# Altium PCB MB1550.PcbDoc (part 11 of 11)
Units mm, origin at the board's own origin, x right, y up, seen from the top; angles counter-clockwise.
Board outline 154.81 x 170.69 mm, 6 copper layers (Top Layer, Signal Layer 1, Signal Layer 2, Signal Layer 3, Signal Layer 4, Bottom Layer), stack 1.49 mm thick; 810 components, 633 nets, 2973 pads, 2150 vias.
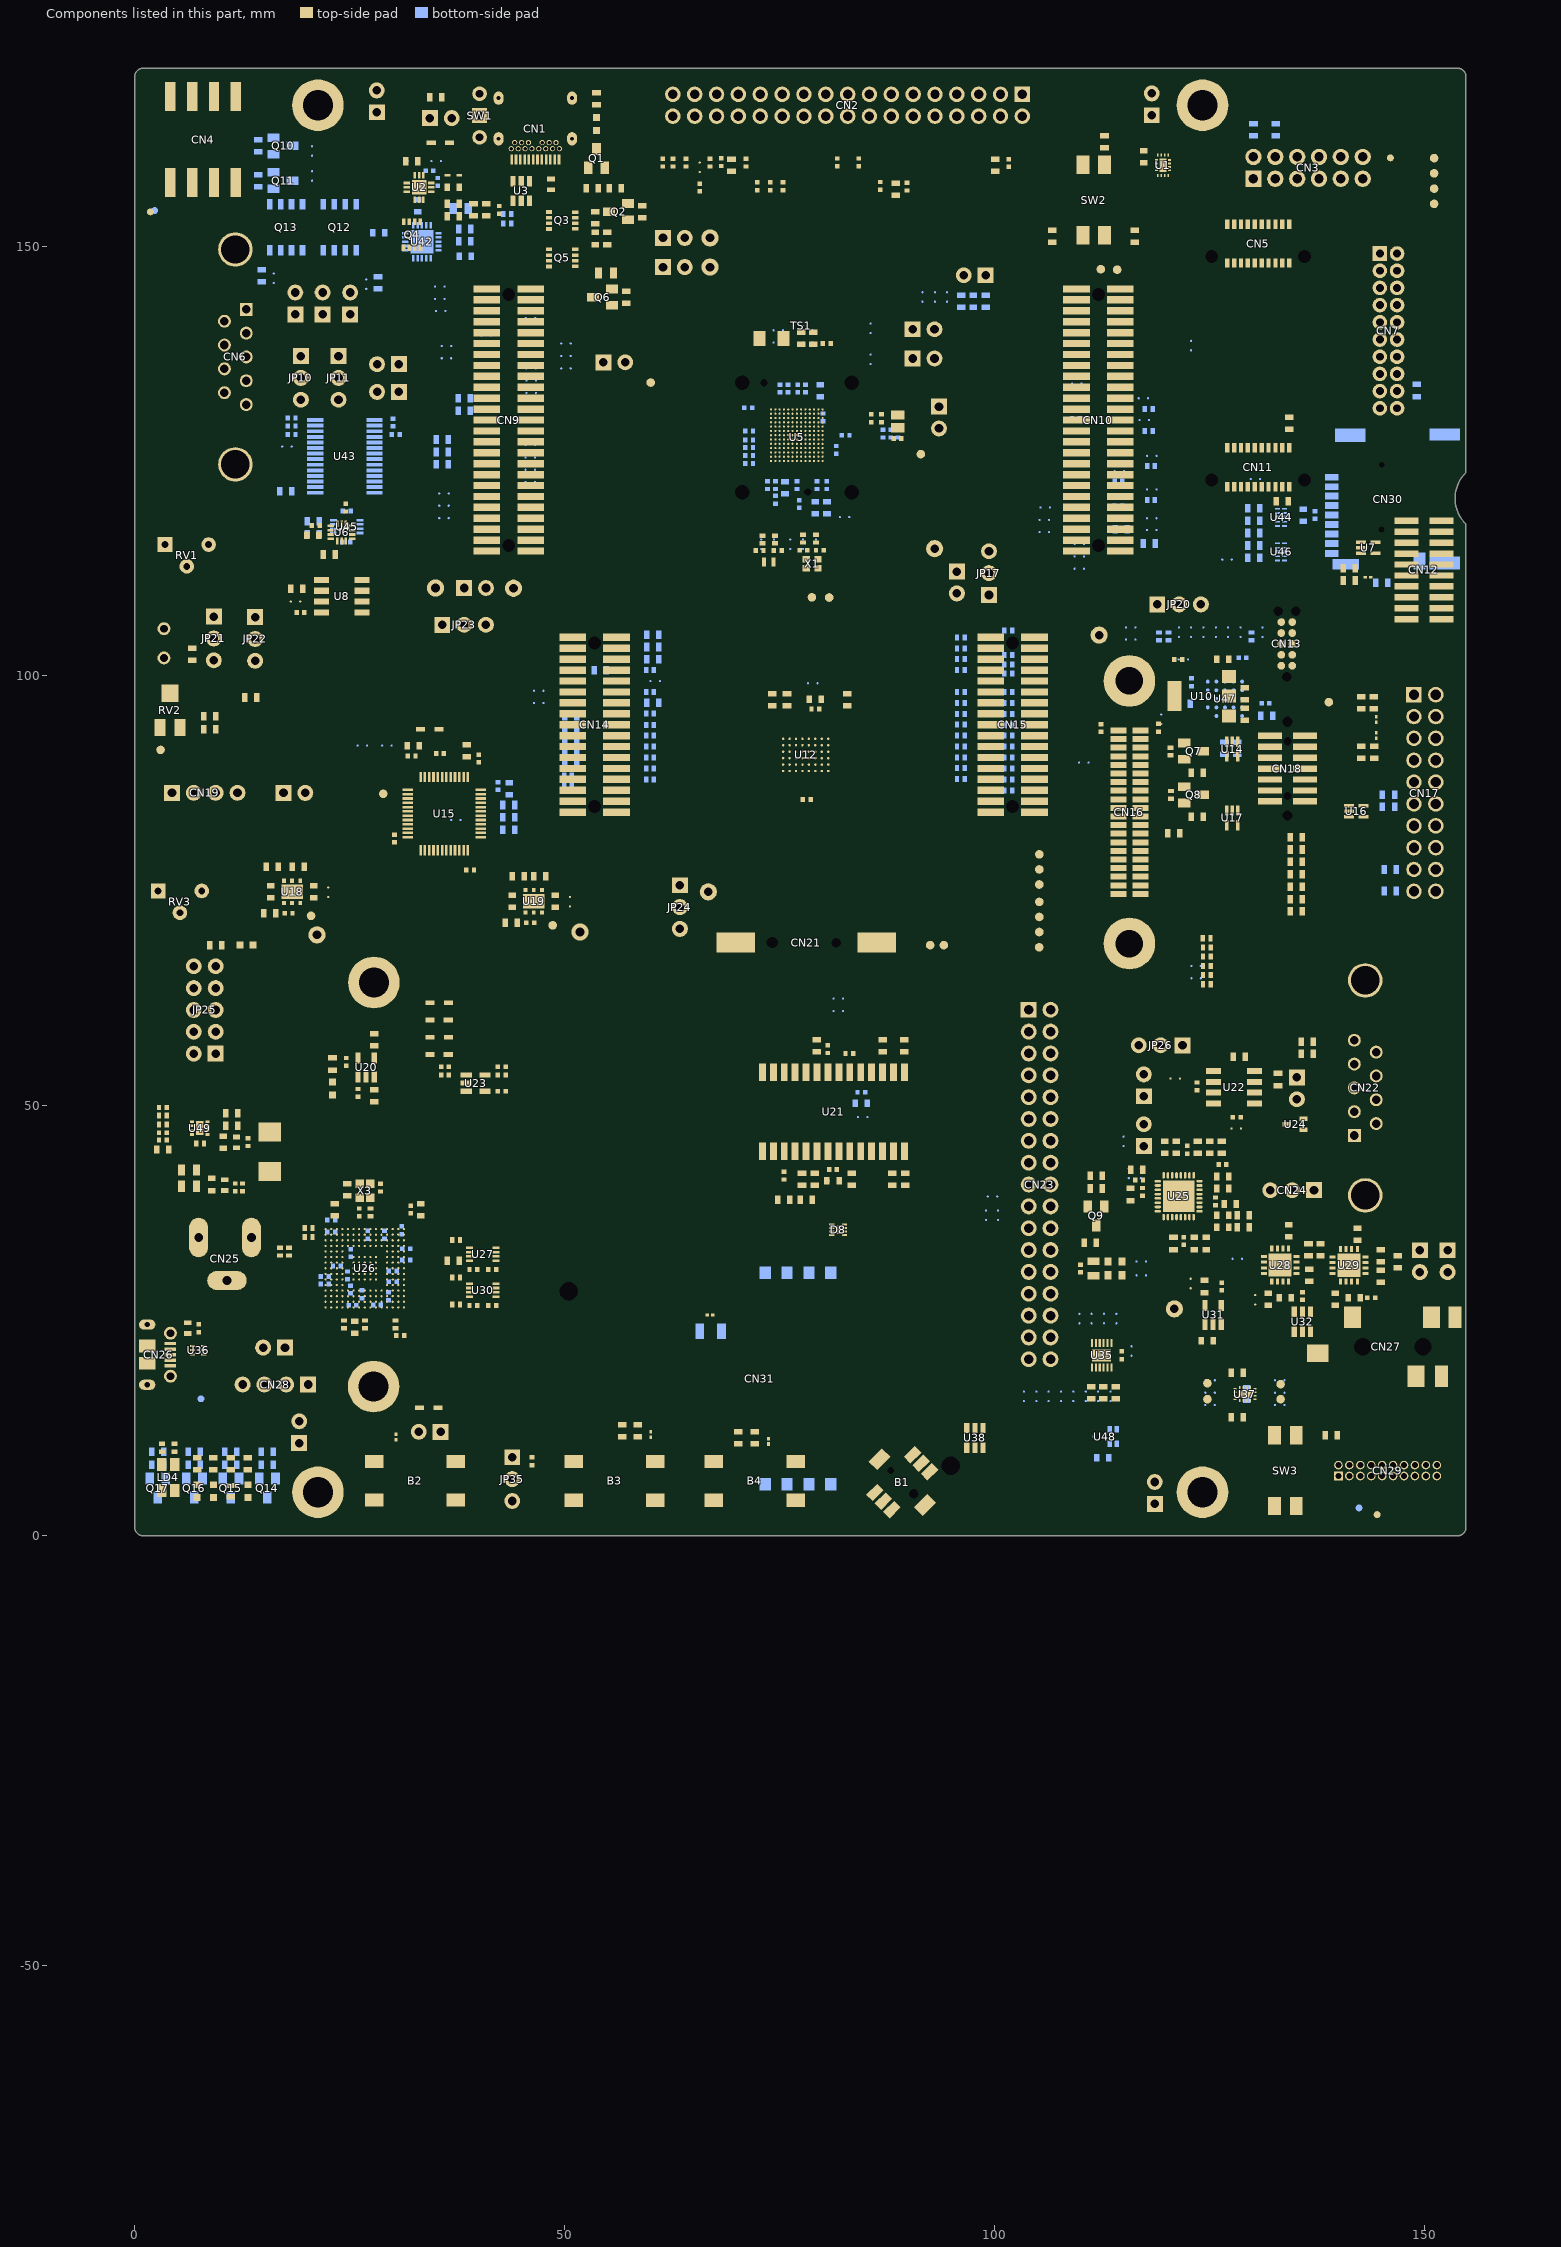
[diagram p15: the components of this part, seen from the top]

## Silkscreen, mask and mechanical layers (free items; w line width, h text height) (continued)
Drill Drawing:
  drawing of 548 lines, arcs and shapes, not listed
  text "PCB SPECIFICATIONS :" at 100.8,238.2 h3
  text "MINIMUM PARAMETERS" at 251.25,238.042 h3
  text "A.   MATERIAL :" at 100.8,234.2 h3
  text "FR-4" at 139.3,234.2 h3
  text "TG-170" at 155.8,234.2 h3
  text "X  TG-150" at 174.05,234.2 h3
  text "TG-140" at 190.05,234.2 h3
  text "DEFAULT" at 251.25,232.542 h3
  text "B.   MATERIAL FAMILY :" at 100.8,231.2 h3
  text "N/A" at 139.3,231.2 h3
  text "C.   SOLDERMASK COLOR :" at 100.8,228.2 h3
  text "GREEN" at 139.3,228.2 h3
  text "X  BLUE" at 155.8,228.2 h3
  text "RED" at 174.05,228.2 h3
  text "BLACK" at 190.05,228.2 h3
  text "TRACKS : 0.09mm           / GAPS : 0.12mm" at 251.25,226.792 h3
  text "D.   SILKSCREEN COLOR :" at 100.8,225.2 h3
  text "X  WHITE" at 139.3,225.2 h3
  text "YELLOW" at 155.8,225.2 h3
  text "BLACK" at 174.05,225.2 h3
  text "E.   SURFACE FINISH :" at 100.8,222.2 h3
  text "X  ENIG" at 139.3,222.2 h3
  text "IMMERSION SILVER" at 155.8,222.2 h3
  text "IMMERSION TIN" at 190.05,222.2 h3
  text "BGA" at 251.35,222.042 h3
  text "HASL" at 139.3,219.2 h3
  text "HASL (PB-FREE)" at 155.8,219.2 h3
  text "GOLDEN FINGER" at 190.05,219.2 h3
  text "TRACKS : 0.080mm           / GAPS : 0.085mm" at 251.35,216.292 h3
  text "F.   IMPEDANCE CONTROL :" at 100.8,216.2 h3
  text "NO" at 139.3,216.2 h3
  text "X  YES  (SEE IMPEDANCE TABLE FOR DETAIL INFORMATION)" at 155.8,216.2 h3
  text "G.   THROUGH VIA :" at 100.8,213.2 h3
  text "PLUG THE VIAS WHICH ARE COVERED WITH SOLDERMASK ONE OR TWO SIDE." at 139.3,213.2 h3
  text "PLUG MATERIAL :" at 139.3,210.2 h3
  text "X  SOLDERMASK" at 164.8,210.2 h3
  text "NON-CONDUCTIVE EPOXY." at 190.05,210.2 h3
  text "H.   STACK-UP :" at 100.8,207.2 h3
  text "SEE LAYER STACK-UP SEQUENCE FOR OVERALL THICKNESS." at 139.3,207.2 h3
  text "THE COMPONENTS WITH PLATED THROUGH HOLE (PTH) MAY BE WELDED (CABLED) IN \"PIN-IN-PASTE\" MODE (IF NECESSARY)" at 102.228,201.929 h3
  text "Layer" at 178.93,180.7 h2
  text "Name" at 187.303,180.7 h2
  text "Material" at 203.5,180.7 h2
  text "Thickness" at 218.055,180.7 h2
  text "Constant" at 230.009,180.7 h2
  text "Board Layer Stack" at 241.073,180.7 h2
  text "Top Overlay" at 187.303,176.7 h2
  text "Top Solder" at 187.303,172.7 h2
  text "Solder Resist" at 203.5,172.7 h2
  text "0,015mm" at 218.055,172.7 h2
  text "3,5" at 230.009,172.7 h2
  text "1" at 178.93,168.7 h2
  text "Top Layer" at 187.303,168.7 h2
  text "Copper" at 203.5,168.7 h2
  text "0,035mm" at 218.055,168.7 h2
  text "Dielectric 1" at 187.303,164.7 h2
  text "TU-768P" at 203.5,164.7 h2
  text "0,070mm" at 218.055,164.7 h2
  text "4,2" at 230.009,164.7 h2
  text "2" at 178.928,160.7 h2
  text "Signal Layer 1" at 187.303,160.7 h2
  text "Copper" at 203.5,160.7 h2
  text "0,035mm" at 218.055,160.7 h2
  text "Dielectric 2" at 187.303,156.7 h2
  text "TU-768P" at 203.5,156.7 h2
  text "0,070mm" at 218.055,156.7 h2
  text "4,2" at 230.009,156.7 h2
  text "3" at 178.93,152.7 h2
  text "Signal Layer 2" at 187.303,152.7 h2
  text "Copper" at 203.5,152.7 h2
  text "0,035mm" at 218.055,152.7 h2
  text "Dielectric 3" at 187.303,148.7 h2
  text "TU-768" at 203.5,148.7 h2
  text "1,000mm" at 218.055,148.7 h2
  text "4,2" at 230.009,148.7 h2
  text "4" at 178.93,144.7 h2
  text "Signal Layer 3" at 187.303,144.7 h2
  text "Copper" at 203.5,144.7 h2
  text "0,035mm" at 218.055,144.7 h2
  text "Dielectric 4" at 187.303,140.7 h2
  text "TU-768P" at 203.5,140.7 h2
  text "0,070mm" at 218.055,140.7 h2
  text "4,2" at 230.009,140.7 h2
  text "5" at 178.93,136.7 h2
  text "Signal Layer 4" at 187.303,136.7 h2
  text "Copper" at 203.5,136.7 h2
  text "0,035mm" at 218.055,136.7 h2
  text "Dielectric 5" at 187.303,132.7 h2
  text "TU-768P" at 203.5,132.7 h2
  text "0,070mm" at 218.055,132.7 h2
  text "4,2" at 230.009,132.7 h2
  text "6" at 178.93,128.7 h2
  text "Bottom Layer" at 187.303,128.7 h2
  text "Copper" at 203.5,128.7 h2
  text "0,035mm" at 218.055,128.7 h2
  text "Bottom Solder" at 187.303,124.7 h2
  text "Solder Resist" at 203.5,124.7 h2
  text "0,015mm" at 218.055,124.7 h2
  text "3,5" at 230.009,124.7 h2
  text "Bottom Overlay" at 187.303,120.7 h2
  text "Symbol" at 178.061,109.95 h1.83
  text "Count" at 185.221,109.95 h1.83
  text "Hole Size" at 193.424,109.95 h1.83
  text "Plated" at 208.095,109.95 h1.83
  text "Hole Type" at 214.381,109.95 h1.83
  text "Drill Layer Pair" at 223.532,109.95 h1.83
  text "Via/Pad" at 240.875,109.95 h1.83
  text "1" at 185.221,106.796 h1.52
  text "0,325mm (12,80mil)" at 193.424,106.796 h1.52
  text "NPTH" at 208.095,106.796 h1.52
  text "Round" at 214.381,106.796 h1.52
  text "Top Layer - Bottom Layer" at 223.532,106.796 h1.52
  text "Pad" at 240.875,106.796 h1.52
  text "1" at 185.221,103.642 h1.52
  text "0,650mm (25,59mil)" at 193.424,103.642 h1.52
  text "NPTH" at 208.095,103.642 h1.52
  text "Round" at 214.381,103.642 h1.52
  text "Top Layer - Bottom Layer" at 223.532,103.642 h1.52
  text "Pad" at 240.875,103.642 h1.52
  text "1" at 185.221,100.488 h1.52
  text "0,700mm (27,56mil)" at 193.424,100.488 h1.52
  text "NPTH" at 208.095,100.488 h1.52
  text "Round" at 214.381,100.488 h1.52
  text "Top Layer - Bottom Layer" at 223.532,100.488 h1.52
  text "Pad" at 240.875,100.488 h1.52
  text "1" at 185.221,97.333 h1.52
  text "0,800mm (31,50mil)" at 193.424,97.333 h1.52
  text "NPTH" at 208.095,97.333 h1.52
  text "Round" at 214.381,97.333 h1.52
  text "Top Layer - Bottom Layer" at 223.532,97.333 h1.52
  text "Pad" at 240.875,97.333 h1.52
  text "1" at 185.221,94.179 h1.52
  text "1,300mm (51,18mil)" at 193.424,94.179 h1.52
  text "NPTH" at 208.095,94.179 h1.52
  text "Round" at 214.381,94.179 h1.52
  text "Top Layer - Bottom Layer" at 223.532,94.179 h1.52
  text "Pad" at 240.875,94.179 h1.52
  text "2" at 185.221,91.025 h1.52
  text "0,600mm (23,62mil)" at 193.424,91.025 h1.52
  text "PTH" at 208.095,91.025 h1.52
  text "Slot" at 214.381,91.025 h1.52
  text "Top Layer - Bottom Layer" at 223.532,91.025 h1.52
  text "Pad" at 240.875,91.025 h1.52
  text "2" at 185.221,87.871 h1.52
  text "0,850mm (33,47mil)" at 193.424,87.871 h1.52
  text "NPTH" at 208.095,87.871 h1.52
  text "Round" at 214.381,87.871 h1.52
  text "Top Layer - Bottom Layer" at 223.532,87.871 h1.52
  text "Pad" at 240.875,87.871 h1.52
  text "I" at 177.653,87.617 h1.4
  text "2" at 185.221,84.717 h1.52
  text "0,970mm (38,19mil)" at 193.424,84.717 h1.52
  text "NPTH" at 208.095,84.717 h1.52
  text "Round" at 214.381,84.717 h1.52
  text "Top Layer - Bottom Layer" at 223.532,84.717 h1.52
  text "Pad" at 240.875,84.717 h1.52
  text "C" at 177.419,84.463 h1.4
  text "2" at 185.221,81.562 h1.52
  text "1,190mm (46,85mil)" at 193.424,81.562 h1.52
  text "NPTH" at 208.095,81.562 h1.52
  text "Round" at 214.381,81.562 h1.52
  text "Top Layer - Bottom Layer" at 223.532,81.562 h1.52
  text "Pad" at 240.875,81.562 h1.52
  text "B" at 177.419,81.309 h1.4
  text "2" at 185.221,78.408 h1.52
  text "2,000mm (78,74mil)" at 193.424,78.408 h1.52
  text "NPTH" at 208.095,78.408 h1.52
  text "Round" at 214.381,78.408 h1.52
  text "Top Layer - Bottom Layer" at 223.532,78.408 h1.52
  text "Pad" at 240.875,78.408 h1.52
  text "G" at 177.419,78.154 h1.4
  text "2" at 185.221,75.254 h1.52
  text "2,150mm (84,65mil)" at 193.424,75.254 h1.52
  text "NPTH" at 208.095,75.254 h1.52
  text "Round" at 214.381,75.254 h1.52
  text "Top Layer - Bottom Layer" at 223.532,75.254 h1.52
  text "Pad" at 240.875,75.254 h1.52
  text "2" at 185.221,72.1 h1.52
  text "3,200mm (125,98mil)" at 193.424,72.1 h1.52
  text "PTH" at 208.095,72.1 h1.52
  text "Round" at 214.381,72.1 h1.52
  text "Top Layer - Bottom Layer" at 223.532,72.1 h1.52
  text "Pad" at 240.875,72.1 h1.52
  text "3" at 185.221,68.946 h1.52
  text "1,000mm (39,37mil)" at 193.424,68.946 h1.52
  text "PTH" at 208.095,68.946 h1.52
  text "Slot" at 214.381,68.946 h1.52
  text "Top Layer - Bottom Layer" at 223.532,68.946 h1.52
  text "Pad" at 240.875,68.946 h1.52
  text "F" at 177.419,68.692 h1.4
  text "4" at 185.221,65.791 h1.52
  text "0,450mm (17,72mil)" at 193.424,65.791 h1.52
  text "PTH" at 208.095,65.791 h1.52
  text "Slot" at 214.381,65.791 h1.52
  text "Top Layer - Bottom Layer" at 223.532,65.791 h1.52
  text "Pad" at 240.875,65.791 h1.52
  text "J" at 177.419,65.538 h1.4
  text "4" at 185.221,62.637 h1.52
  text "1,700mm (66,93mil)" at 193.424,62.637 h1.52
  text "NPTH" at 208.095,62.637 h1.52
  text "Round" at 214.381,62.637 h1.52
  text "Top Layer - Bottom Layer" at 223.532,62.637 h1.52
  text "Pad" at 240.875,62.637 h1.52
  text "K" at 177.419,62.383 h1.4
  text "4" at 185.221,59.483 h1.52
  text "3,300mm (129,92mil)" at 193.424,59.483 h1.52
  text "PTH" at 208.095,59.483 h1.52
  text "Round" at 214.381,59.483 h1.52
  text "Top Layer - Bottom Layer" at 223.532,59.483 h1.52
  text "Pad" at 240.875,59.483 h1.52
  text "D" at 177.419,59.229 h1.4
  text "5" at 185.221,56.329 h1.52
  text "1,100mm (43,31mil)" at 193.424,56.329 h1.52
  text "NPTH" at 208.095,56.329 h1.52
  text "Round" at 214.381,56.329 h1.52
  text "Top Layer - Bottom Layer" at 223.532,56.329 h1.52
  text "Pad" at 240.875,56.329 h1.52
  text "6" at 185.221,53.175 h1.52
  text "0,800mm (31,50mil)" at 193.424,53.175 h1.52
  text "PTH" at 208.095,53.175 h1.52
  text "Round" at 214.381,53.175 h1.52
  text "Top Layer - Bottom Layer" at 223.532,53.175 h1.52
  text "Pad" at 240.875,53.175 h1.52
  text "6" at 185.221,50.02 h1.52
  text "3,500mm (137,79mil)" at 193.424,50.02 h1.52
  text "PTH" at 208.095,50.02 h1.52
  text "Round" at 214.381,50.02 h1.52
  text "Top Layer - Bottom Layer" at 223.532,50.02 h1.52
  text "Pad" at 240.875,50.02 h1.52
  text "12" at 185.221,46.866 h1.52
  text "1,500mm (59,06mil)" at 193.424,46.866 h1.52
  text "NPTH" at 208.095,46.866 h1.52
  text "Round" at 214.381,46.866 h1.52
  text "Top Layer - Bottom Layer" at 223.532,46.866 h1.52
  text "Pad" at 240.875,46.866 h1.52
  text "E" at 177.419,46.612 h1.4
  text "14" at 185.221,43.712 h1.52
  text "0,400mm (15,75mil)" at 193.424,43.712 h1.52
  text "PTH" at 208.095,43.712 h1.52
  text "Round" at 214.381,43.712 h1.52
  text "Top Layer - Bottom Layer" at 223.532,43.712 h1.52
  text "Pad" at 240.875,43.712 h1.52
  text "20" at 185.221,40.558 h1.52
  text "0,700mm (27,56mil)" at 193.424,40.558 h1.52
  text "PTH" at 208.095,40.558 h1.52
  text "Round" at 214.381,40.558 h1.52
  text "Top Layer - Bottom Layer" at 223.532,40.558 h1.52
  text "Pad" at 240.875,40.558 h1.52
  text "H" at 177.419,40.304 h1.4
  text "20" at 185.221,37.404 h1.52
  text "1,200mm (47,24mil)" at 193.424,37.404 h1.52
  text "PTH" at 208.095,37.404 h1.52
  text "Round" at 214.381,37.404 h1.52
  text "Top Layer - Bottom Layer" at 223.532,37.404 h1.52
  text "Pad" at 240.875,37.404 h1.52
  text "A" at 177.419,37.15 h1.4
  text "27" at 185.221,34.249 h1.52
  text "0,900mm (35,43mil)" at 193.424,34.249 h1.52
  text "PTH" at 208.095,34.249 h1.52
  text "Round" at 214.381,34.249 h1.52
  text "Top Layer - Bottom Layer" at 223.532,34.249 h1.52
  text "Pad" at 240.875,34.249 h1.52
  text "80" at 185.221,31.095 h1.52
  text "1,100mm (43,31mil)" at 193.424,31.095 h1.52
  text "PTH" at 208.095,31.095 h1.52
  text "Round" at 214.381,31.095 h1.52
  text "Top Layer - Bottom Layer" at 223.532,31.095 h1.52
  text "Pad" at 240.875,31.095 h1.52
  text "133" at 185.221,27.941 h1.52
  text "1,000mm (39,37mil)" at 193.424,27.941 h1.52
  text "PTH" at 208.095,27.941 h1.52
  text "Round" at 214.381,27.941 h1.52
  text "Top Layer - Bottom Layer" at 223.532,27.941 h1.52
  text "Pad" at 240.875,27.941 h1.52
  text "373" at 185.221,24.787 h1.52
  text "0,100mm (3,94mil)" at 193.424,24.787 h1.52
  text "PTH" at 208.095,24.787 h1.52
  text "Round" at 214.381,24.787 h1.52
  text "(Mixed)" at 223.532,24.787 h1.52
  text "Via" at 240.875,24.787 h1.52
  text "M" at 177.419,24.533 h1.4
  text "1777" at 185.221,21.633 h1.52
  text "0,200mm (7,87mil)" at 193.424,21.633 h1.52
  text "PTH" at 208.095,21.633 h1.52
  text "Round" at 214.381,21.633 h1.52
  text "Top Layer - Bottom Layer" at 223.532,21.633 h1.52
  text "Via" at 240.875,21.633 h1.52
  text "L" at 177.419,21.379 h1.4
  text "2507 Total" at 185.221,18.478 h1.52
  text "Slot definitions :" at 178.061,16.27 h1.52
  text "Routed Path Length" at 188.455,16.27 h1.52
  text "= Calculated from tool start centre position to tool end centre position." at 201.332,16.27 h1.52
  text "Hole Length" at 188.455,15.009 h1.52
  text "= Routed Path Length + Tool Size = Slot length as defined in the PCB layout" at 196.551,15.009 h1.52
  text ".Layer_Name" at 34.834,-69.2 h3
  text ".DRL" at 76.528,-69.2 h3
M20-Top Title Box:
  circle w0.254: c112.838,-75.921 r1.3
  region: 98.36,-77.014 87.604,-77.014 88.597,-74.521 96.455,-74.521 96.904,-73.762 99.112,-76.31
  region: 112.363,-68.684 96.836,-68.684 96.142,-70.46 94.931,-71.685 93.534,-69.825 93.534,-68.174 94.677,-66.777 96.113,-66.398 112.363,-66.398
  lines w0.254: 88.597,-74.521 97.389,-74.521 94.323,-70.983 cw(c96.127,-69.039) 96.367,-66.398 113.131,-66.398 112.369,-68.684 ; 91.911,-66.151 cw(c94.337,-67.122) 94.574,-64.519 ; 91.95,-66.119 87.604,-77.014 106.926,-77.014 ccw(c107.175,-74.279) 109.724,-75.299 ; 93.69,-70.053 99.112,-76.31 ; 93.944,-70.053 99.249,-76.175 ; 93.944,-69.799 99.249,-75.921 ; 94.042,-68.684 107.035,-68.684 ; 94.071,-69.672 99.376,-75.794 ; 94.198,-69.545 99.503,-75.667 ; 94.325,-69.418 99.63,-75.54 ; 94.452,-69.291 99.757,-75.413 ; 94.507,-67.339 99.812,-73.46 ; 94.575,-64.519 114.024,-64.519 109.725,-75.297 ; 94.579,-69.164 99.829,-75.223 ; 94.579,-68.91 99.884,-75.032 ; 94.579,-68.656 99.884,-74.778 ; 94.579,-67.767 99.884,-73.889 ; 94.706,-68.529 100.011,-74.651 ; 94.706,-68.148 100.011,-74.27 ; 96.078,-74.534 ccw(c96.183,-73.999) 96.48,-73.542 ; 97.164,-68.671 ccw(c97.138,-69.238) 96.808,-69.7 99.173,-72.429 cw(c97.369,-74.373) 98.101,-76.921 ; 103.445,-76.81 106.335,-68.43 ; 103.668,-76.76 106.537,-68.439 ; 103.795,-76.76 106.664,-68.439 ; 104.049,-76.76 106.918,-68.439 ; 104.303,-76.76 107.172,-68.439 ; 104.557,-76.76 107.426,-68.439 ; 104.811,-76.76 107.68,-68.439 ; 105.065,-76.76 107.934,-68.439 ; 105.319,-76.76 108.188,-68.439 ; 105.573,-76.76 108.442,-68.439 ; 105.781,-76.81 108.671,-68.43 ; 108.671,-68.684 112.363,-68.684 ; 111.695,-68.682 112.457,-66.396 ; 111.861,-68.684 112.623,-66.398 ; 112.115,-68.684 112.877,-66.398
  lines w0.3: 25.833,-80.9 115.833,-80.9 115.833,-60.9 25.833,-60.9 ; 25.833,-75.9 85.833,-75.9 ; 25.833,-70.9 85.833,-70.9 ; 25.833,-65.9 85.833,-65.9 ; 25.834,-80.9 25.834,-60.9 ; 65.833,-80.9 65.833,-65.9 ; 85.833,-80.9 85.833,-60.9 ; 103.445,-76.81 105.781,-76.81
  text "Project: '.Board_Name'" at 26.834,-64.116 h3
  text "Layer:" at 26.834,-69.2 h3
  text "Gerber:" at 66.822,-69.2 h3
  text "Variant: '.VariantName'" at 26.834,-74.2 h3
  text "Ref: MB1550" at 66.949,-74.2 h3
  text "R" at 112.33,-76.683 h1.52
  text "Date: 2020-NOV-13" at 26.834,-79.2 h3
  text "Rev: '.Board_PCB_Revision'" at 66.892,-79.2 h3
M21-Bottom Title Box:
  circle w0.254: c29.016,-75.921 r1.3
  region: 29.491,-68.684 45.018,-68.684 45.713,-70.46 46.923,-71.685 48.32,-69.825 48.32,-68.174 47.177,-66.777 45.741,-66.398 29.491,-66.398
  region: 43.494,-77.014 54.25,-77.014 53.257,-74.521 45.399,-74.521 44.951,-73.762 42.742,-76.31
  lines w0.254: 28.977,-66.398 29.739,-68.684 ; 29.231,-66.398 29.993,-68.684 ; 29.397,-66.396 30.159,-68.682 ; 29.485,-68.684 28.723,-66.398 45.487,-66.398 cw(c45.727,-69.039) 47.531,-70.983 44.465,-74.521 53.257,-74.521 ; 29.491,-68.684 33.183,-68.684 ; 32.129,-75.297 27.83,-64.519 47.279,-64.519 ; 32.13,-75.299 ccw(c34.679,-74.279) 34.928,-77.014 54.25,-77.014 49.904,-66.119 ; 33.183,-68.43 36.073,-76.81 ; 33.412,-68.439 36.281,-76.76 ; 33.666,-68.439 36.535,-76.76 ; 33.92,-68.439 36.789,-76.76 ; 34.174,-68.439 37.043,-76.76 ; 34.428,-68.439 37.297,-76.76 ; 34.682,-68.439 37.551,-76.76 ; 34.819,-68.684 47.812,-68.684 ; 34.936,-68.439 37.805,-76.76 ; 35.19,-68.439 38.059,-76.76 ; 35.317,-68.439 38.186,-76.76 ; 35.519,-68.43 38.409,-76.81 ; 41.843,-74.651 47.148,-68.529 ; 41.843,-74.27 47.148,-68.148 ; 41.97,-75.032 47.275,-68.91 ; 41.97,-74.778 47.275,-68.656 ; 41.97,-73.889 47.275,-67.767 ; 42.025,-75.223 47.275,-69.164 ; 42.043,-73.46 47.348,-67.339 ; 42.097,-75.413 47.402,-69.291 ; 42.224,-75.54 47.529,-69.418 ; 42.351,-75.667 47.656,-69.545 ; 42.478,-75.794 47.783,-69.672 ; 42.605,-76.175 47.91,-70.053 ; 42.605,-75.921 47.91,-69.799 ; 42.742,-76.31 48.164,-70.053 ; 43.753,-76.921 cw(c44.485,-74.373) 42.681,-72.429 45.046,-69.7 ccw(c44.716,-69.238) 44.69,-68.671 ; 45.374,-73.542 ccw(c45.672,-73.999) 45.777,-74.534 ; 47.281,-64.519 cw(c47.517,-67.122) 49.943,-66.151
  lines w0.3: 36.073,-76.81 38.409,-76.81 ; 55.833,-80.9 55.833,-60.9 ; 55.833,-75.9 115.833,-75.9 ; 55.833,-70.9 115.833,-70.9 ; 55.833,-65.9 115.833,-65.9 ; 75.833,-80.9 75.833,-65.9 ; 25.833,-80.9 25.833,-60.9 115.833,-60.9 115.833,-80.9 25.833,-80.9
  text "Project: '.Board_Name'" at 114.639,-64.116 h3
  text "Gerber:" at 74.651,-69.2 h3
  text "Layer:" at 114.639,-69.2 h3
  text "Ref: MB1550" at 74.651,-74.2 h3
  text "Variant: '.VariantName'" at 114.639,-74.2 h3
  text "R" at 29.524,-76.683 h1.52
  text "Rev: '.Board_PCB_Revision'" at 74.708,-79.2 h3
  text "Date: 2020-NOV-13" at 114.639,-79.2 h3

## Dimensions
154.813,169.688 to 0,169.688 on M2-Board Dimensions
1,170.688 to 1,0 on M2-Board Dimensions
